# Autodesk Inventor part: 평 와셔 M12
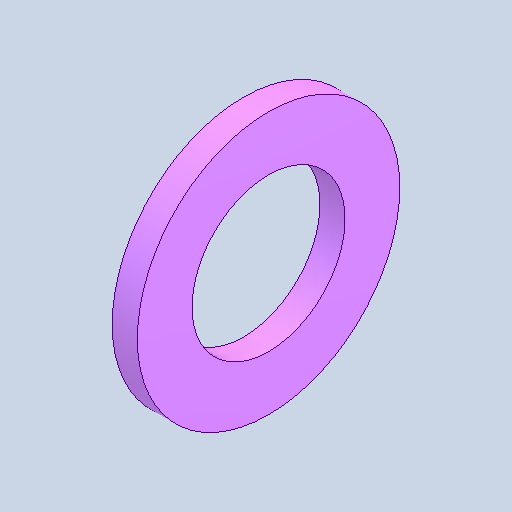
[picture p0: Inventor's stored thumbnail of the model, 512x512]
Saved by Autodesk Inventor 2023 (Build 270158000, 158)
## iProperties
Created: 2026-06
Part Number: 평 와셔 M12
Material: 강철, 연강
Description: 평면 와셔
Document SubType Name: Modeling
Designer: 4강의실
Density: 7.85 g/cm^3
Appearance: 기본값
Author: jhkim
Sending System: Autodesk Inventor 2027
Preprocessor: ST-DEVELOPER v20.1
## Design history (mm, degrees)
feature "Solid1"
node "솔리드1"
